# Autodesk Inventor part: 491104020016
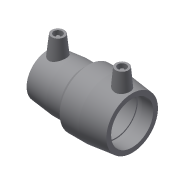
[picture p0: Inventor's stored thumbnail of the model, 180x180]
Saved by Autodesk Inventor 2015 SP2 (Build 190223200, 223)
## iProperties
Created: 2017-06
Part Number: 491104020016
Material: Generic
Description: PLASSON REDUCING COUPLER 20-16
Document SubType Name: Modeling
Designer: KIM
Mass: 54.8237 g
Surface Area: 155.252 cm^2
Volume: 54.8237 cm^3
Density: 1 g/cm^3
Appearance: Default
Author: KIM
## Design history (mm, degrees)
derived "491104.ipt"
feature "Solid1::491104.ipt"
tag "TaggingFeature1"
body "Solid1"
other parameters: "d_1" = 16, "L_" = 71, "L_2" = 35, "D_1" = 36, "A_1" = 39, "d_2" = 12, "L_1" = 35, "A_" = 39, "D_" = 36, "d0" = 71, "d2" = 36, "d3" = 35, "d4" = 21, "d5" = 32.4, "d7" = 16, "d8" = 168 deg, "d10" = 14, "d11" = 4.66667, "d13" = 71, "d14" = 17.6296, "d15" = 35, "d18" = 16, "d19" = 1.75, "d20" = 168 deg, "d22" = 108.92847, "d25" = 135 deg, "d29" = 39, "d30" = 15, "d31" = 24.85, "d34" = 6 deg, "d35" = 15, "d38" = 30.2, "d39" = 5 deg, "d41" = 4, "d42" = 14, "d43" = 0, "d45" = 4, "d46" = 14, "d47" = 0, "d48" = 36, "d50" = 36, "d52" = 14.4, "d53" = 14, "d54" = 4.66667, "d55" = 168 deg, "d56" = 21, "d57" = 35, "d58" = 32.4, "d59" = 0.98, "d60" = 135 deg, "d61" = 39, "d62" = 15, "d64" = 4, "d66" = 5 deg, "d67" = 14, "d68" = 0, "d69" = 24.85, "d70" = 36, "d71" = 36, "d73" = 33.84, "d76" = 1.75, "d77" = 168 deg, "d79" = 1.75, "d80" = 35, "d81" = 14.4, "d82" = 33.84, "d83" = 120 deg, "d88" = 15, "d89" = 28, "d90" = 5 deg, "d92" = 4, "d93" = 14, "d94" = 0, "d95" = 3, "d96" = 0, "d97" = 3, "d98" = 0, "d99" = 10.15, "d100" = 2.5375, "d101" = 32.8248, "d102" = 20 deg, "d103" = 10.15, "d104" = 2.5375, "d105" = 32.8248, "d106" = 3.60705, "d107" = 3, "d108" = 0, "d109" = 3, "d110" = 0
